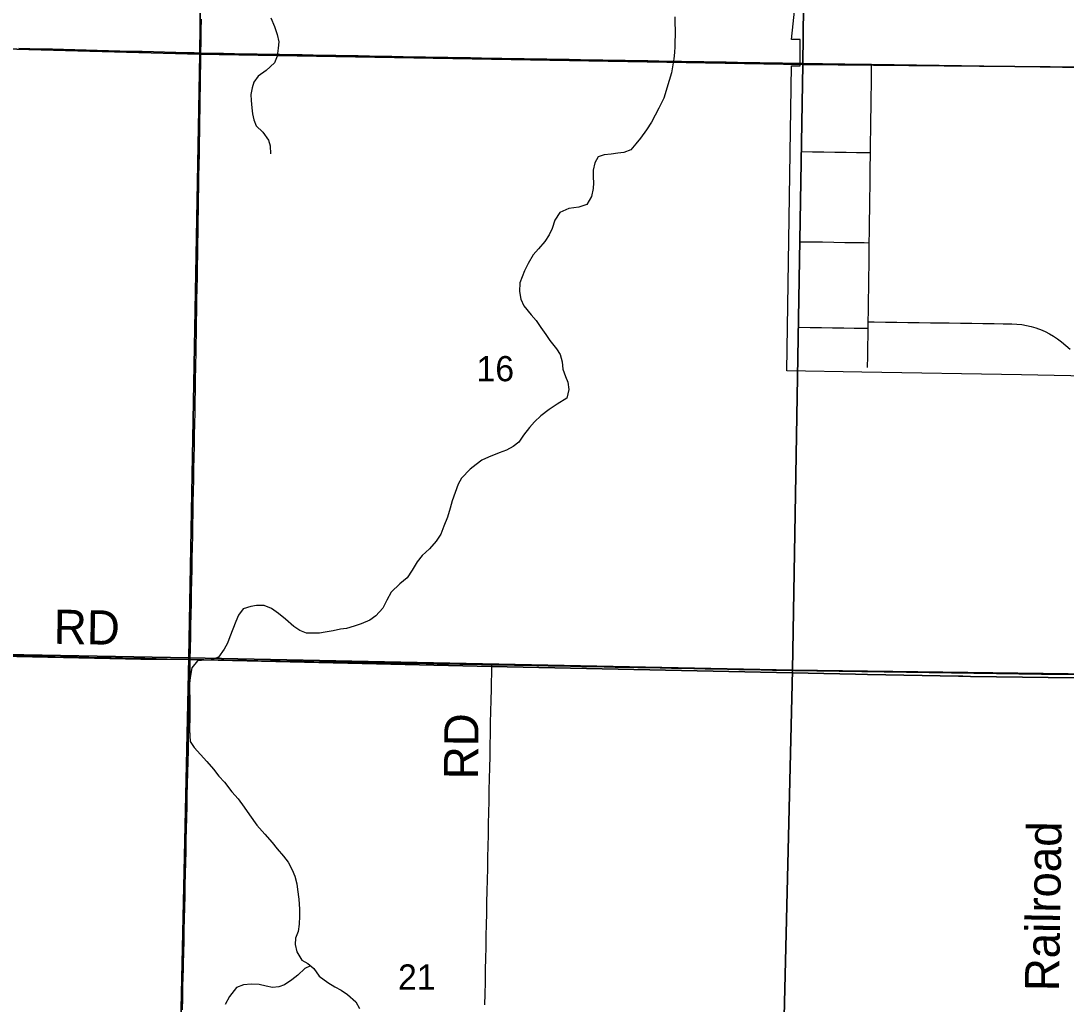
# Model space of a CAD drawing. Extents: x -11.1 to 34, y -3.9 to 22.
# Drawn here: x 3.076 to 4.812, y 14.712 to 16.345 of the extents above; entities that cross this region are included whole.
import ezdxf

# ---------------------------------------------------------------- set-up
doc = ezdxf.new("R2010")
doc.units = 0
for name, color, linetype in [('GM_X_City_Street', 7, 'Continuous'), ('GM_X_Corporation', 7, 'Continuous'), ('GM_X_County_Road', 7, 'Continuous'), ('GM_X_County_Road_Text', 7, 'Continuous'), ('GM_X_Minor_River', 7, 'Continuous'), ('GM_X_Rail_Line_Text', 7, 'Continuous'), ('GM_X_Section_Text', 7, 'Continuous'), ('GM_X_State_Route', 7, 'Continuous'), ('GM_X_Township_Road', 7, 'Continuous'), ('GM_X_Township_Road_Text', 7, 'Continuous')]:
    doc.layers.add(name, color=color, linetype=linetype)

msp = doc.modelspace()

# ---------------------------------------------------------------- linework, layer by layer
at = {"layer": 'GM_X_City_Street'}
msp.add_line((4.4833, 15.835), (4.4835, 15.8457), dxfattribs=at)
for points in [[(4.4835, 15.8457), (4.4837, 15.8643), (4.484, 15.8829), (4.4842, 15.9016), (4.4845, 15.9202), (4.4847, 15.9389), (4.4849, 15.9575), (4.4851, 15.9673), (4.4852, 15.977), (4.4855, 15.9957), (4.4857, 16.0143), (4.486, 16.033), (4.4862, 16.0516), (4.4865, 16.0702), (4.4867, 16.0889), (4.4869, 16.1075), (4.4871, 16.1171), (4.4872, 16.1267), (4.4874, 16.1453), (4.4877, 16.1639), (4.4879, 16.1826), (4.4882, 16.2012), (4.4884, 16.2199), (4.4887, 16.2385), (4.4888, 16.2484), (4.4889, 16.2583), (4.4891, 16.2734)], [(4.3722, 16.1283), (4.3909, 16.1281), (4.4095, 16.1278), (4.4282, 16.1275), (4.4468, 16.1272), (4.4642, 16.127), (4.4815, 16.1267), (4.4872, 16.1267)], [(4.3702, 15.9787), (4.3889, 15.9784), (4.4075, 15.9782), (4.4262, 15.9779), (4.4448, 15.9776), (4.4608, 15.9774), (4.4768, 15.9772), (4.4852, 15.977)], [(4.4835, 15.8457), (4.4934, 15.8455), (4.5121, 15.8452), (4.5307, 15.845), (4.5493, 15.8447), (4.568, 15.8444), (4.5866, 15.8442), (4.6022, 15.844), (4.6179, 15.8437), (4.6365, 15.8435), (4.6552, 15.8432), (4.6738, 15.8429), (4.6924, 15.8427), (4.7073, 15.8425), (4.7221, 15.8422), (4.7302, 15.8419), (4.7383, 15.841), (4.7463, 15.8397), (4.7542, 15.8378), (4.7619, 15.8355), (4.7659, 15.8341), (4.7696, 15.8327), (4.777, 15.8295), (4.7842, 15.8258), (4.7912, 15.8216), (4.7979, 15.8171), (4.8044, 15.8121), (4.8189, 15.8004)], [(4.3684, 15.8367), (4.387, 15.8364), (4.4056, 15.8361), (4.4243, 15.8358), (4.4429, 15.8356), (4.4599, 15.8353), (4.4768, 15.8351), (4.4833, 15.835)], [(4.4824, 15.7697), (4.4827, 15.7883), (4.4829, 15.807), (4.4831, 15.821), (4.4833, 15.835)]]:
    msp.add_lwpolyline(points, dxfattribs=at)
at = {"layer": 'GM_X_Corporation'}
for points in [[(2.1, 18.3243), (2.1, 15.3106), (2.171, 15.3082), (2.3479, 15.3077), (2.7781, 15.2969), (3.0179, 15.2909), (3.2754, 15.2855), (3.2832, 15.2853), (3.3566, 15.2846), (3.8581, 15.2731), (4.4622, 15.2602), (4.4824, 15.2598), (4.6334, 15.2569), (4.6407, 15.2568), (4.6535, 15.2566), (4.8684, 15.2535), (5.0169, 15.252), (5.2769, 15.2522), (6.3599, 15.2448), (7.3508, 15.2219)], [(4.8741, 15.7548), (4.7379, 15.7575), (4.4726, 15.7622), (4.3481, 15.7643), (4.3561, 16.2709), (4.3703, 16.2707), (4.3702, 16.3146), (4.356, 16.3148), (4.3787, 16.5288), (4.3805, 16.6238), (4.7548, 16.6175), (4.7564, 16.7751), (4.8221, 16.7767)], [(7.3508, 15.2219), (6.3599, 15.2448), (5.2769, 15.2522), (5.0169, 15.252), (4.8684, 15.2535), (4.6535, 15.2566), (4.6407, 15.2568), (4.6334, 15.2569), (4.4824, 15.2598), (4.4622, 15.2602), (3.8581, 15.2731), (3.3566, 15.2846), (3.2832, 15.2853), (3.2754, 15.2855), (3.0179, 15.2909), (2.7781, 15.2969), (2.3479, 15.3077), (2.171, 15.3082), (2.1, 15.3106), (2.1, 14.1), (7.332, 14.1)]]:
    msp.add_lwpolyline(points, dxfattribs=at)
for points in [[(3.3852, 17.301), (3.3734, 16.2901), (2.3594, 16.3176), (2.3686, 17.3282)], [(3.3852, 17.301), (4.3866, 17.2855), (4.3746, 16.2728), (3.3734, 16.2901)], [(5.385, 17.2762), (5.3715, 16.2638), (4.3746, 16.2728), (4.3866, 17.2855)], [(3.3734, 16.2901), (3.3556, 15.2873), (2.3502, 15.3059), (2.3594, 16.3176)], [(4.3746, 16.2728), (4.3579, 15.2669), (3.3556, 15.2873), (3.3734, 16.2901)], [(4.3746, 16.2728), (5.3715, 16.2638), (5.3559, 15.2538), (4.3579, 15.2669)], [(2.3502, 15.3059), (3.3556, 15.2873), (3.3334, 14.2733), (2.3217, 14.2992)], [(4.3579, 15.2669), (4.3335, 14.2541), (3.3334, 14.2733), (3.3556, 15.2873)], [(5.3559, 15.2538), (5.3338, 14.242), (4.3335, 14.2541), (4.3579, 15.2669)]]:
    msp.add_lwpolyline(points, close=True, dxfattribs=at)
at = {"layer": 'GM_X_County_Road'}
msp.add_lwpolyline([(3.0586, 15.2914), (3.0772, 15.291), (3.0959, 15.2906), (3.1145, 15.2902), (3.1332, 15.2898), (3.1518, 15.2894), (3.1704, 15.289), (3.1891, 15.2886), (3.2077, 15.2882), (3.2263, 15.2878), (3.245, 15.2875), (3.2636, 15.2871), (3.2822, 15.2867), (3.3009, 15.2863), (3.3195, 15.2859), (3.3381, 15.2855), (3.348, 15.2853), (3.3578, 15.2851), (3.3764, 15.2847), (3.3951, 15.2844), (3.4137, 15.2841), (3.4324, 15.2837), (3.451, 15.2834), (3.4697, 15.2831), (3.4883, 15.2827), (3.5069, 15.2824), (3.5256, 15.2821), (3.5442, 15.2817), (3.5629, 15.2814), (3.5815, 15.2811), (3.6001, 15.2807), (3.6188, 15.2804), (3.6374, 15.2801), (3.6561, 15.2797), (3.6747, 15.2794), (3.6933, 15.2791), (3.712, 15.2788), (3.7306, 15.2784), (3.7493, 15.2781), (3.7679, 15.2778), (3.7866, 15.2774), (3.8052, 15.2771), (3.8238, 15.2768), (3.8412, 15.2764), (3.8585, 15.2761), (3.8771, 15.2758), (3.8958, 15.2754), (3.9144, 15.2751), (3.933, 15.2747), (3.9517, 15.2744), (3.9703, 15.274), (3.9889, 15.2737), (4.0076, 15.2733), (4.0262, 15.2729), (4.0448, 15.2726), (4.0635, 15.2722), (4.0821, 15.2719), (4.1007, 15.2715), (4.1194, 15.2712), (4.138, 15.2708), (4.1567, 15.2705), (4.1753, 15.2701), (4.1939, 15.2698), (4.2126, 15.2694), (4.2312, 15.269), (4.2498, 15.2687), (4.2685, 15.2683), (4.2871, 15.268), (4.3057, 15.2676), (4.3244, 15.2672), (4.3426, 15.2669), (4.3608, 15.2666), (4.3794, 15.2663), (4.398, 15.266), (4.4167, 15.2657), (4.4353, 15.2655), (4.454, 15.2652), (4.4726, 15.2649), (4.4913, 15.2647), (4.5099, 15.2644), (4.5285, 15.2641), (4.5472, 15.2639), (4.5658, 15.2636), (4.5845, 15.2633), (4.6031, 15.263), (4.6217, 15.2628), (4.6404, 15.2625), (4.659, 15.2622), (4.6777, 15.262), (4.6963, 15.2617), (4.7149, 15.2614), (4.7336, 15.2611), (4.7522, 15.2609), (4.7709, 15.2606), (4.7895, 15.2603), (4.8082, 15.2601), (4.8268, 15.2598)], dxfattribs=at)
at = {"layer": 'GM_X_Minor_River'}
for points in [[(3.4917, 16.3508), (3.4974, 16.3362), (3.5021, 16.3228), (3.5045, 16.3105), (3.5039, 16.2999), (3.5021, 16.287), (3.4976, 16.2757), (3.4837, 16.2631), (3.4706, 16.2535), (3.4632, 16.2438), (3.4603, 16.234), (3.4585, 16.223), (3.4587, 16.2131), (3.46, 16.2012), (3.4613, 16.1909), (3.4633, 16.181), (3.4669, 16.171), (3.4784, 16.1605), (3.4876, 16.1473), (3.4904, 16.1378), (3.4909, 16.1244)], [(4.1624, 16.3524), (4.1625, 16.3414), (4.1627, 16.33), (4.1621, 16.303), (4.1615, 16.2931), (4.1609, 16.2824), (4.1591, 16.2726), (4.1566, 16.2593), (4.1529, 16.2465), (4.1439, 16.217), (4.1356, 16.2005), (4.1233, 16.1772), (4.1154, 16.1644), (4.1053, 16.1509), (4.0978, 16.1412), (4.0893, 16.1311), (4.0774, 16.1269), (4.0679, 16.1256), (4.0565, 16.1243), (4.0447, 16.1227), (4.0352, 16.1195), (4.0296, 16.1097), (4.0267, 16.0976), (4.0265, 16.0858), (4.0274, 16.0763), (4.0268, 16.0668), (4.0242, 16.0535), (4.0164, 16.0404), (4.003, 16.0361), (3.9863, 16.0339), (3.9713, 16.027), (3.9631, 16.0146), (3.9586, 16.0006), (3.9538, 15.9901), (3.9464, 15.9792), (3.9359, 15.9669), (3.9273, 15.9569), (3.9186, 15.9426), (3.9127, 15.9302), (3.9087, 15.9204), (3.905, 15.9106), (3.9043, 15.8961), (3.9067, 15.8832), (3.9118, 15.8724), (3.924, 15.8573), (3.9321, 15.8476), (3.9398, 15.836), (3.9479, 15.8244), (3.9549, 15.8147), (3.9656, 15.8008), (3.9718, 15.7911), (3.975, 15.7789), (3.9766, 15.7671), (3.9809, 15.7548), (3.9845, 15.7452), (3.9861, 15.733), (3.9828, 15.719), (3.967, 15.7087), (3.9535, 15.6999), (3.94, 15.6892), (3.9295, 15.6795), (3.921, 15.6699), (3.9112, 15.6572), (3.9034, 15.6459), (3.8937, 15.6385), (3.883, 15.6323), (3.8707, 15.6281), (3.8531, 15.6209), (3.842, 15.6158), (3.8324, 15.6088), (3.8223, 15.601), (3.8083, 15.5858), (3.8024, 15.5757), (3.7976, 15.5621), (3.7923, 15.5481), (3.7894, 15.536), (3.7849, 15.5209), (3.7789, 15.5062), (3.7737, 15.4931), (3.7658, 15.4815), (3.7549, 15.4684), (3.7425, 15.4577), (3.7343, 15.4468), (3.726, 15.4333), (3.7178, 15.4206), (3.7058, 15.4102), (3.6915, 15.3965), (3.6843, 15.3834), (3.6776, 15.3698), (3.6659, 15.3572), (3.6559, 15.3502), (3.6414, 15.3441), (3.6299, 15.3402), (3.6173, 15.3363), (3.607, 15.335), (3.5952, 15.3322)], [(3.5952, 15.3322), (3.5819, 15.3299), (3.5723, 15.3286), (3.561, 15.3285), (3.5507, 15.3287), (3.5398, 15.3328), (3.5294, 15.3398), (3.5156, 15.3516), (3.504, 15.361), (3.4924, 15.3692), (3.4804, 15.3744), (3.4675, 15.3743), (3.458, 15.373), (3.4454, 15.3688), (3.4376, 15.3583), (3.4336, 15.3481), (3.4283, 15.335), (3.4235, 15.3222), (3.4195, 15.312), (3.4139, 15.3019), (3.4045, 15.2884), (3.3923, 15.2841), (3.3828, 15.2836), (3.3699, 15.2823), (3.3605, 15.2708), (3.3575, 15.2549), (3.3565, 15.2447), (3.3566, 15.2317), (3.3568, 15.2215), (3.3571, 15.2047), (3.3572, 15.1903), (3.3567, 15.1683), (3.3569, 15.158), (3.3574, 15.1485), (3.364, 15.1388), (3.3747, 15.1272), (3.3851, 15.1152), (3.3962, 15.1027), (3.4054, 15.0908), (3.4147, 15.0807), (3.4268, 15.0648), (3.4372, 15.0535), (3.4471, 15.0396), (3.456, 15.0269), (3.4685, 15.0095), (3.4814, 14.9948), (3.4936, 14.9808), (3.5021, 14.97), (3.5125, 14.9579), (3.5202, 14.9483), (3.5271, 14.9352), (3.5311, 14.9248), (3.5346, 14.9122), (3.5359, 14.9027), (3.5378, 14.8867), (3.5389, 14.8699), (3.539, 14.8582), (3.5387, 14.8449), (3.5366, 14.8328), (3.5325, 14.8218), (3.5319, 14.8112), (3.5347, 14.7994), (3.5427, 14.7851), (3.5528, 14.78), (3.5629, 14.7717), (3.5717, 14.759), (3.5859, 14.748), (3.5975, 14.7413), (3.608, 14.7354), (3.6188, 14.7283), (3.6326, 14.7162), (3.6388, 14.705)], [(3.5576, 14.7761), (3.5481, 14.7717), (3.5361, 14.7602), (3.5264, 14.7528), (3.5141, 14.7444), (3.5045, 14.7408), (3.4943, 14.7399), (3.4837, 14.7424), (3.472, 14.745), (3.4591, 14.7457), (3.4462, 14.7444), (3.4347, 14.7398), (3.4226, 14.7252), (3.4155, 14.7117)]]:
    msp.add_lwpolyline(points, dxfattribs=at)
at = {"layer": 'GM_X_State_Route'}
msp.add_line((4.3752, 16.2751), (4.3887, 16.2749), dxfattribs=at)
for points in [[(3.0729, 16.3003), (3.0915, 16.2998), (3.1101, 16.2993), (3.1288, 16.2988), (3.1474, 16.2983), (3.1661, 16.2978), (3.1847, 16.2974), (3.2033, 16.2969), (3.222, 16.2964), (3.2406, 16.2959), (3.2592, 16.2954), (3.2779, 16.2949), (3.2965, 16.2944), (3.3151, 16.2939), (3.3338, 16.2934), (3.3524, 16.293), (3.364, 16.2927), (3.3755, 16.2924), (3.3942, 16.292), (3.4128, 16.2917), (3.4314, 16.2914), (3.4501, 16.291), (3.4687, 16.2907), (3.4874, 16.2904), (3.506, 16.29), (3.5246, 16.2897), (3.5433, 16.2894), (3.5619, 16.289), (3.5806, 16.2887), (3.5992, 16.2884), (3.6178, 16.288), (3.6365, 16.2877), (3.6551, 16.2874), (3.6738, 16.287), (3.6924, 16.2867), (3.711, 16.2864), (3.7297, 16.286), (3.7483, 16.2857), (3.767, 16.2854), (3.7856, 16.285), (3.8043, 16.2847), (3.8229, 16.2844), (3.8415, 16.2841), (3.8582, 16.2838), (3.8749, 16.2835), (3.8935, 16.2831), (3.9122, 16.2828), (3.9308, 16.2825), (3.9495, 16.2822), (3.9681, 16.2819), (3.9867, 16.2816), (4.0054, 16.2813), (4.024, 16.281), (4.0427, 16.2807), (4.0613, 16.2803), (4.08, 16.28), (4.0986, 16.2797), (4.1172, 16.2794), (4.1359, 16.2791), (4.1545, 16.2788), (4.1669, 16.2786)], [(4.1669, 16.2786), (4.1732, 16.2785), (4.1918, 16.2782), (4.2104, 16.2778), (4.2291, 16.2775), (4.2477, 16.2772), (4.2664, 16.2769), (4.285, 16.2766), (4.3036, 16.2763), (4.3223, 16.276), (4.3409, 16.2756), (4.3576, 16.2754), (4.3742, 16.2751), (4.3752, 16.2751)], [(4.3887, 16.2749), (4.4073, 16.2746), (4.4259, 16.2743), (4.4446, 16.2741), (4.4632, 16.2738), (4.4762, 16.2736), (4.4891, 16.2734), (4.5078, 16.2731), (4.5264, 16.2729), (4.5451, 16.2726), (4.5637, 16.2723), (4.5824, 16.272), (4.5971, 16.2718)], [(4.5971, 16.2718), (4.601, 16.2718), (4.6196, 16.2715), (4.6383, 16.2712), (4.6569, 16.2709), (4.6756, 16.2707), (4.6942, 16.2704), (4.7128, 16.2701), (4.7315, 16.2698), (4.7501, 16.2696), (4.7688, 16.2693), (4.7874, 16.269), (4.806, 16.2688), (4.8236, 16.2685), (4.8411, 16.2682), (4.8597, 16.2672), (4.8783, 16.2661), (4.8871, 16.2656)]]:
    msp.add_lwpolyline(points, dxfattribs=at)
at = {"layer": 'GM_X_Township_Road'}
for points in [[(3.3578, 15.2851), (3.3582, 15.3037), (3.3585, 15.3223), (3.3589, 15.341), (3.3592, 15.3596), (3.3596, 15.3782), (3.3599, 15.3969), (3.3603, 15.4155), (3.3606, 15.4341), (3.361, 15.4528), (3.3613, 15.4714), (3.3617, 15.49), (3.362, 15.5087), (3.3624, 15.5273), (3.3627, 15.546), (3.3631, 15.5646), (3.3634, 15.5832), (3.3638, 15.6019), (3.3642, 15.6205), (3.3645, 15.6391), (3.3649, 15.6578), (3.3652, 15.6764), (3.3656, 15.695), (3.3659, 15.7137), (3.3663, 15.7323), (3.3666, 15.7509), (3.367, 15.7696), (3.3671, 15.7793), (3.3673, 15.7891), (3.3676, 15.8077), (3.3679, 15.8264), (3.3682, 15.845), (3.3685, 15.8637), (3.3688, 15.8823), (3.3692, 15.9009), (3.3695, 15.9196), (3.3698, 15.9382), (3.3701, 15.9569), (3.3704, 15.9755), (3.3707, 15.9941), (3.371, 16.0128), (3.3713, 16.0314), (3.3716, 16.0501), (3.3719, 16.0687), (3.3722, 16.0874), (3.3725, 16.106), (3.3728, 16.1246), (3.3731, 16.1433), (3.3734, 16.1619), (3.3737, 16.1806), (3.374, 16.1992), (3.3743, 16.2178), (3.3746, 16.2365), (3.3749, 16.2551), (3.3752, 16.2737), (3.3755, 16.2924), (3.3757, 16.311), (3.3759, 16.3296), (3.3761, 16.3483)], [(3.3448, 14.7029), (3.3452, 14.7215), (3.3456, 14.7402), (3.3461, 14.7588), (3.3463, 14.7692), (3.3465, 14.7797), (3.347, 14.7983), (3.3474, 14.8169), (3.3478, 14.8356), (3.3482, 14.8542), (3.3486, 14.8728), (3.349, 14.8915), (3.3495, 14.9101), (3.3499, 14.9288), (3.3503, 14.9474), (3.3507, 14.966), (3.3511, 14.9847), (3.3515, 15.0033), (3.352, 15.0219), (3.3524, 15.0406), (3.3528, 15.0592), (3.3532, 15.0778), (3.3536, 15.0965), (3.354, 15.1151), (3.3545, 15.1337), (3.3549, 15.1524), (3.3553, 15.171), (3.3557, 15.1896), (3.3561, 15.2083), (3.3565, 15.2269), (3.3569, 15.2455), (3.3573, 15.2642), (3.3576, 15.2746), (3.3578, 15.2851)], [(3.8469, 14.7109), (3.8473, 14.7295), (3.8477, 14.7482), (3.8479, 14.7589), (3.8481, 14.7697), (3.8485, 14.7883), (3.8489, 14.807), (3.8493, 14.8256), (3.8497, 14.8443), (3.85, 14.8629), (3.8504, 14.8815), (3.8508, 14.9002), (3.8512, 14.9188), (3.8516, 14.9374), (3.8519, 14.9561), (3.8523, 14.9747), (3.8527, 14.9933), (3.8531, 15.012), (3.8535, 15.0306), (3.8538, 15.0492), (3.8542, 15.0679), (3.8546, 15.0865), (3.855, 15.1051), (3.8554, 15.1238), (3.8558, 15.1424), (3.8561, 15.161), (3.8565, 15.1797), (3.8569, 15.1983), (3.8573, 15.2169), (3.8577, 15.2356), (3.8579, 15.2481), (3.8582, 15.2606), (3.8585, 15.2761)]]:
    msp.add_lwpolyline(points, dxfattribs=at)

# ---------------------------------------------------------------- texts
at = {"layer": 'GM_X_County_Road_Text'}
msp.add_text('RD', height=0.05682, rotation=359.0118, dxfattribs=at).set_placement((3.1306, 15.3109))
at = {"layer": 'GM_X_Rail_Line_Text'}
msp.add_text('Railroad', height=0.05663, rotation=89.1027, dxfattribs=at).set_placement((4.8001, 14.7334))
at = {"layer": 'GM_X_Section_Text'}
for s, p in [('16', (3.8331, 15.7469)), ('21', (3.7027, 14.7364))]:
    msp.add_text(s, height=0.04186, rotation=0, dxfattribs=at).set_placement(p)
at = {"layer": 'GM_X_Township_Road_Text'}
msp.add_text('RD', height=0.05682, rotation=89.5063, dxfattribs=at).set_placement((3.8356, 15.0854))

doc.saveas('drawing.dxf')
